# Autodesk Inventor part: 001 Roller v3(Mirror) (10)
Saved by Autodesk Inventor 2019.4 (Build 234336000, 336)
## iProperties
Created: 2020-06
Part Number: 001 Roller v3(Mirror) (10)
Material: Generic
Document SubType Name: Modeling
Designer: Administrator
Density: 1 g/cm^3
Appearance: Default
Title: 001 Roller v3(Mirror) (10)
Author: Administrator
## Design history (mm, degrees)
